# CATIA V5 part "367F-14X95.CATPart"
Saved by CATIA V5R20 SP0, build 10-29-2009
Part number: 367F-14X95
Definition: NONE
Nomenclature: 367F-14X95
Source: Unknown
Description: 367F-14X95
Bounding box of the stored display mesh (mm): x 0 to 95, y -14 to 14, z -14 to 14
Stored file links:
  C:\Users\Utente\Desktop\IO LAVORO\3D X SITO CF\X SITO\PLASTICA\3D files 367\367F-14X95.CATPart
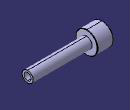
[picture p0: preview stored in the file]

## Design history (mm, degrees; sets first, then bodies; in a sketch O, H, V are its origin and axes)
Body1 "367F-14X95" (main body)
  Solid1: solid without history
